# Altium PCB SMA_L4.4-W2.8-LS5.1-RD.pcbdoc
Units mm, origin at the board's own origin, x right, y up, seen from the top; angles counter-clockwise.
Board outline 19.1 x 15.6 mm, 2 copper layers (Top Layer, Bottom Layer), stack 0 mm thick; 1 components, 0 nets, 2 pads, 0 vias.
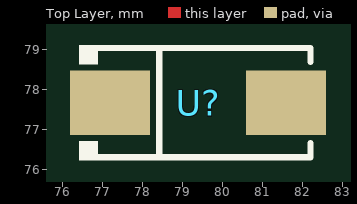
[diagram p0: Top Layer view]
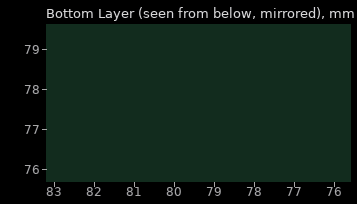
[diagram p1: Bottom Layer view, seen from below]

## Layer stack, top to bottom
Top Layer: signal copper (thickness not stored)
Bottom Layer: signal copper (thickness not stored)

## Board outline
88.95,69.85 69.85,69.85 69.85,85.45 88.95,85.45

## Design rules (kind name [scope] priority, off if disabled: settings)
PasteMaskExpansion "Paste Mask Expansion" [All] p1: expansion=0
SolderMaskExpansion "Solder Mask Expansion" [IsVia] p1: expansion=-25.4 istentingtop=TRUE
SolderMaskExpansion "Solder Mask Expansion" [All] p2: expansion=0.051 istentingtop=FALSE

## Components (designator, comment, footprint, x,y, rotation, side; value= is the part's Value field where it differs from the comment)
U? "" SMA_L4.4-W2.8-LS5.1-RD 79.4,77.66 r0 top

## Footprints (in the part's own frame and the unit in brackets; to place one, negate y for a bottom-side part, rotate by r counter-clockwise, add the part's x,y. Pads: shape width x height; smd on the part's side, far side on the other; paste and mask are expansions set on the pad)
SMA_L4.4-W2.8-LS5.1-RD [mm]
  rect 2x1.62 smd: 1(-2.2,0) 2(2.2,0)
  silkscreen extent -2.97,-1.44 2.81,1.44

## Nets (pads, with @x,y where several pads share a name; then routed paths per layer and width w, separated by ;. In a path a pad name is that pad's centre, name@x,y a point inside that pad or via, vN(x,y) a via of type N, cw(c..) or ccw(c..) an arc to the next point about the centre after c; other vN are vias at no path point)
pads on no net: U?.1 U?.2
